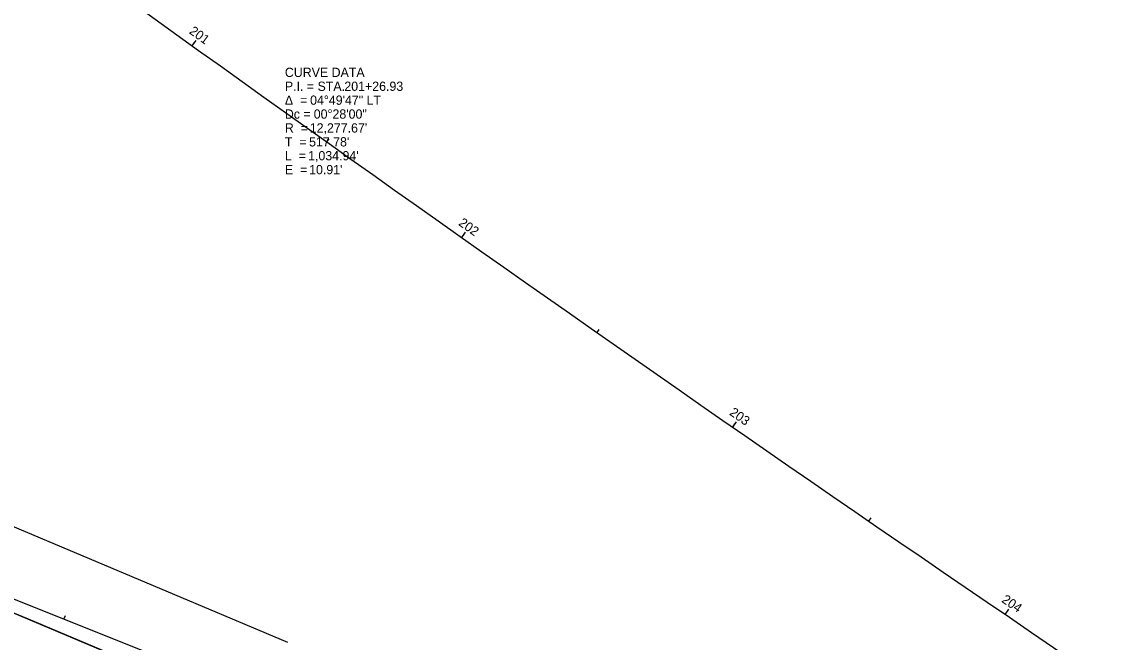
# Model space of a CAD drawing. Extents: x 1323137 to 1326838, y 458936 to 461644.
# Drawn here: x 1325220.9 to 1325549.7, y 459774 to 459961.6 of the extents above; entities that cross this region are included whole.
import ezdxf

# ---------------------------------------------------------------- set-up
doc = ezdxf.new("R2010")
doc.units = 0
for name, color, linetype in [('CM_Corridor_Final', 7, 'Continuous'), ('CM_Corridor_Range_Final', 7, 'Continuous'), ('Default', 7, 'Continuous'), ('DT_P_Tie', 7, 'Continuous'), ('SG_P_Conduit', 7, 'Continuous'), ('SG_P_Mast_Arm', 7, 'Continuous'), ('SN_P_Signs', 7, 'Continuous'), ('SN_X_Public', 7, 'Continuous'), ('UT_P_Electric_Cells', 7, 'Continuous')]:
    doc.layers.add(name, color=color, linetype=linetype)

msp = doc.modelspace()

# ---------------------------------------------------------------- linework, layer by layer
at = {"layer": 'CM_Corridor_Range_Final'}
for p, q in [((1325272.44, 459954.34), (1325273.61, 459955.96)), ((1325313.13, 459925.27), (1325313.82, 459926.25)), ((1325353.92, 459896.36), (1325355.08, 459898)), ((1325394.84, 459867.63), (1325395.53, 459868.61)), ((1325435.87, 459839.06), (1325437.01, 459840.7)), ((1325477.02, 459810.65), (1325477.7, 459811.64)), ((1325518.29, 459782.42), (1325519.41, 459784.07))]:
    msp.add_line(p, q, dxfattribs=at)
at = {"layer": 'Default'}
msp.add_line((1325001.32, 459873.45), (1325293.97, 459757.01), dxfattribs=at)
msp.add_lwpolyline([(1325451.7, 459681.24), (1325442.79, 459685.53), (1325433.79, 459689.8), (1325424.78, 459694.02), (1325415.73, 459698.2), (1325406.67, 459702.34), (1325397.58, 459706.44), (1325388.48, 459710.51), (1325379.35, 459714.54), (1325370.21, 459718.54), (1325361.06, 459722.52), (1325351.89, 459726.48), (1325342.71, 459730.41), (1325333.52, 459734.33), (1325324.32, 459738.24), (1325315.11, 459742.13), (1325305.9, 459746.02), (1325296.69, 459749.9), (1325222.91, 459780.98), (1325213.53, 459784.78), (1325076.26, 459836.24)], dxfattribs=at)
msp.add_arc((1332431.06, 469929.07), 12277.67, 232.043309, 236.873031, dxfattribs=at)
at = {"layer": 'DT_P_Tie'}
for p, q in [((1325087.43, 459864.09), (1325301.25, 459774.02)), ((1325087.43, 459864.09), (1325301.25, 459774.02)), ((1325038.48, 459858.66), (1325291.94, 459751.9)), ((1325038.48, 459858.66), (1325291.94, 459751.9))]:
    msp.add_line(p, q, dxfattribs=at)
at = {"layer": 'SG_P_Conduit'}
msp.add_line((1325001.32, 459873.45), (1325293.97, 459757.01), dxfattribs=at)
at = {"layer": 'SG_P_Mast_Arm'}
msp.add_line((1325233.61, 459781.03), (1325234.05, 459782.15), dxfattribs=at)
at = {"layer": 'SN_P_Signs'}
msp.add_line((1325001.32, 459873.45), (1325293.97, 459757.01), dxfattribs=at)
msp.add_arc((1332431.06, 469929.07), 12277.67, 232.043309, 236.873031, dxfattribs=at)
at = {"layer": 'SN_X_Public'}
for p, q in [((1325272.44, 459954.34), (1325273.14, 459955.31)), ((1325353.92, 459896.36), (1325354.62, 459897.35)), ((1325435.87, 459839.06), (1325436.56, 459840.04)), ((1325518.29, 459782.42), (1325518.96, 459783.41))]:
    msp.add_line(p, q, dxfattribs=at)

# ---------------------------------------------------------------- texts
at = {"layer": 'CM_Corridor_Final'}
for s, p in [('CURVE DATA', (1325300.43, 459944.91)), ('P.I. = STA. ', (1325300.43, 459940.71)), ('201+26.93', (1325318.42, 459940.71)), ('Δ  = ', (1325300.43, 459936.51)), ('04°49\'47" LT', (1325308.07, 459936.51)), ('Dc = ', (1325300.43, 459932.31)), ('00°28\'00"', (1325309.17, 459932.31)), ('R  = ', (1325300.43, 459928.11)), ("12,277.67'", (1325307.96, 459928.11)), ('T  = ', (1325300.43, 459923.91)), ("517.78'", (1325307.75, 459923.91)), ('L  = ', (1325300.43, 459919.71)), ("1,034.94'", (1325307.46, 459919.71)), ('E  = ', (1325300.43, 459915.51)), ("10.91'", (1325307.77, 459915.51))]:
    msp.add_text(s, height=2.8, dxfattribs=at).set_placement(p)
at = {"layer": 'CM_Corridor_Range_Final'}
for s, rotation, p in [('201', 324.3339, (1325271.28, 459958.25)), ('202', 324.8006, (1325352.74, 459900.26)), ('203', 325.2673, (1325434.67, 459842.93)), ('204', 325.7339, (1325516.98, 459786.33))]:
    msp.add_text(s, height=2.8, rotation=rotation, dxfattribs=at).set_placement(p)
at = {"layer": 'UT_P_Electric_Cells'}
for s, p in [('CURVE DATA', (1325300.43, 459944.91)), ('P.I. = STA. ', (1325300.43, 459940.71)), ('201+26.93', (1325318.42, 459940.71)), ('Δ  = ', (1325300.43, 459936.51)), ('04°49\'47" LT', (1325308.07, 459936.51)), ('Dc = ', (1325300.43, 459932.31)), ('00°28\'00"', (1325309.17, 459932.31)), ('R  = ', (1325300.43, 459928.11)), ("12,277.67'", (1325307.96, 459928.11)), ('T  = ', (1325300.43, 459923.91)), ("517.78'", (1325307.75, 459923.91)), ('L  = ', (1325300.43, 459919.71)), ("1,034.94'", (1325307.46, 459919.71)), ('E  = ', (1325300.43, 459915.51)), ("10.91'", (1325307.77, 459915.51))]:
    msp.add_text(s, height=2.8, dxfattribs=at).set_placement(p)

doc.saveas('drawing.dxf')
